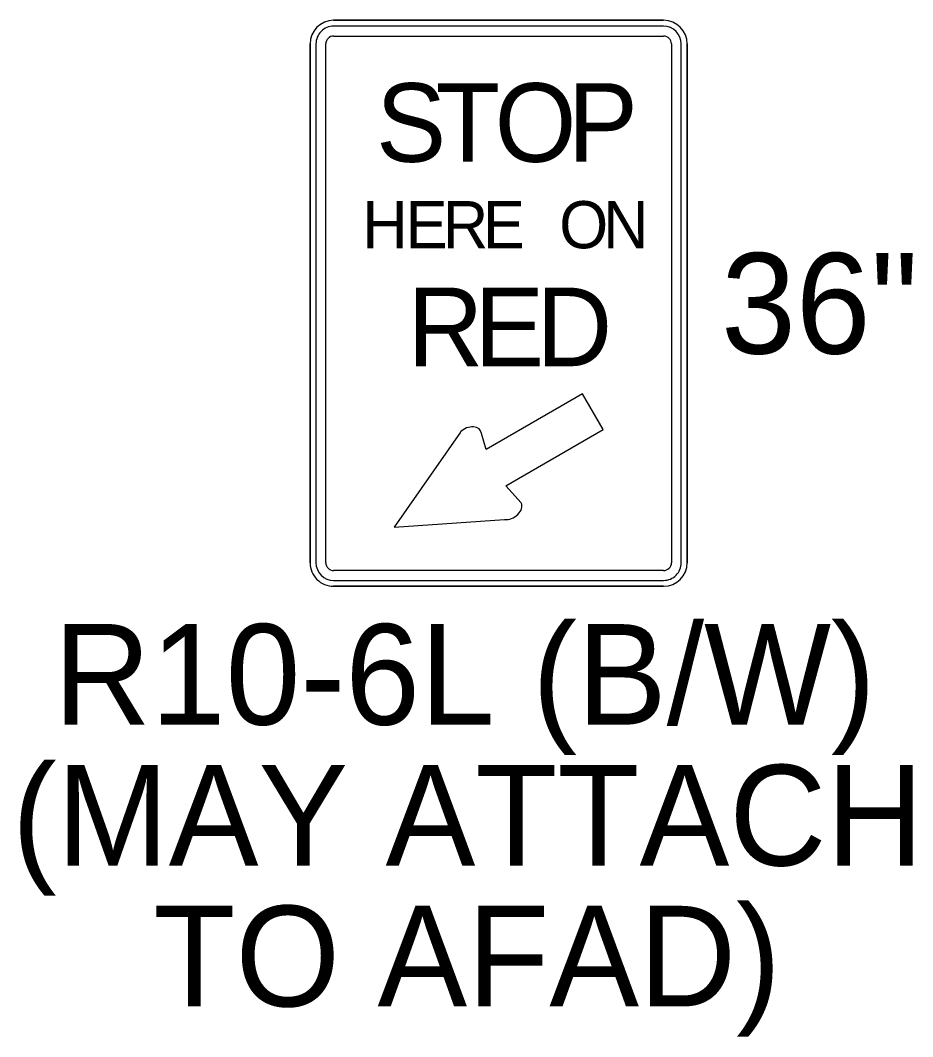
# Model space of a CAD drawing. Extents: x 99999.1 to 100095.7, y 99995 to 100010.7.
# Drawn here: x 100043.892 to 100044.602, y 100003.772 to 100004.58 of the extents above; entities that cross this region are included whole.
import ezdxf

# ---------------------------------------------------------------- set-up
doc = ezdxf.new("R2010")
doc.units = 0
doc.layers.add('TR_SN_ConstructionSigns', color=7, linetype='Continuous')

msp = doc.modelspace()

# ---------------------------------------------------------------- linework, layer by layer
at = {"layer": 'TR_SN_ConstructionSigns'}
for p, q in [((100044.40413, 100004.57961), (100044.14163, 100004.57961)), ((100044.14163, 100004.57961), (100044.40413, 100004.57961)), ((100044.40413, 100004.57961), (100044.14163, 100004.57961)), ((100044.40413, 100004.57493), (100044.14163, 100004.57493)), ((100044.14163, 100004.56711), (100044.40413, 100004.56711)), ((100044.12288, 100004.56086), (100044.12288, 100004.14836)), ((100044.12288, 100004.14836), (100044.12288, 100004.56086)), ((100044.12288, 100004.56086), (100044.12288, 100004.14836)), ((100044.12756, 100004.56086), (100044.12756, 100004.14836)), ((100044.13538, 100004.14836), (100044.13538, 100004.56086)), ((100044.41038, 100004.56086), (100044.41038, 100004.14836)), ((100044.41819, 100004.14836), (100044.41819, 100004.56086)), ((100044.42288, 100004.14836), (100044.42288, 100004.56086)), ((100044.42288, 100004.56086), (100044.42288, 100004.14836)), ((100044.42288, 100004.14836), (100044.42288, 100004.56086)), ((100044.33959, 100004.28269), (100044.26297, 100004.23846)), ((100044.356, 100004.25428), (100044.33959, 100004.28269)), ((100044.24244, 100004.2523), (100044.18976, 100004.1766)), ((100044.26297, 100004.23846), (100044.2592, 100004.25114)), ((100044.27857, 100004.20957), (100044.356, 100004.25428)), ((100044.29088, 100004.19589), (100044.27857, 100004.20957)), ((100044.18976, 100004.1766), (100044.27762, 100004.1827)), ((100044.40413, 100004.14211), (100044.14163, 100004.14211)), ((100044.14163, 100004.1343), (100044.40413, 100004.1343)), ((100044.14163, 100004.12961), (100044.40413, 100004.12961)), ((100044.40413, 100004.12961), (100044.14163, 100004.12961)), ((100044.14163, 100004.12961), (100044.40413, 100004.12961))]:
    msp.add_line(p, q, dxfattribs=at)
for centre, radius, start, end in [((100044.14163, 100004.56086), 0.01875, 90, 180), ((100044.14163, 100004.56086), 0.01875, 90, 180), ((100044.14163, 100004.56086), 0.01875, 90, 180), ((100044.14163, 100004.56086), 0.01406, 90, 180.00001), ((100044.40413, 100004.56086), 0.01875, 0, 90), ((100044.40413, 100004.56086), 0.01875, 0, 90), ((100044.40413, 100004.56086), 0.01875, 0, 90), ((100044.40413, 100004.56086), 0.01406, 0, 90), ((100044.14163, 100004.56086), 0.00625, 90, 180.00001), ((100044.40413, 100004.56086), 0.00625, 0, 90), ((100044.14163, 100004.14836), 0.01875, 180, 270.00001), ((100044.14163, 100004.14836), 0.01875, 180, 270.00001), ((100044.14163, 100004.14836), 0.01875, 180, 270.00001), ((100044.14163, 100004.14836), 0.01406, 180.00001, 270), ((100044.14163, 100004.14836), 0.00625, 180.00001, 270), ((100044.40413, 100004.14836), 0.01875, 270.00001, 0.00001), ((100044.40413, 100004.14836), 0.01875, 270.00001, 0.00001), ((100044.40413, 100004.14836), 0.01875, 270.00001, 0.00001), ((100044.40413, 100004.14836), 0.01406, 270, 0.00001), ((100044.40413, 100004.14836), 0.00625, 270, 0.00001)]:
    msp.add_arc(centre, radius, start, end, dxfattribs=at)
for centre, major_axis, start_param, end_param in [((100044.24915, 100004.24797), (0.00934, 0.00539), 5.977036, 8.198856), ((100044.28158, 100004.19094), (-0.00913, -0.00527), 0.771965, 3.092601)]:
    msp.add_ellipse(centre, major_axis=major_axis, ratio=0.700347, start_param=start_param, end_param=end_param, dxfattribs=at)

# ---------------------------------------------------------------- texts
for s, height, p in [('S', 0.0625, (100044.17538, 100004.46711)), ('T', 0.0625, (100044.22288, 100004.46711)), ('O', 0.0625, (100044.26975, 100004.46711)), ('P', 0.0625, (100044.32788, 100004.46711)), ('H', 0.0375, (100044.16431, 100004.39836)), ('E', 0.0375, (100044.19881, 100004.39836)), ('R', 0.0375, (100044.22844, 100004.39836)), ('E', 0.0375, (100044.26031, 100004.39836)), ('O', 0.0375, (100044.32106, 100004.39836)), ('N', 0.0375, (100044.35594, 100004.39836)), ('R', 0.0625, (100044.20038, 100004.30461)), ('E', 0.0625, (100044.2535, 100004.30461)), ('D', 0.0625, (100044.30288, 100004.30461))]:
    msp.add_text(s, height=height, dxfattribs=at).set_placement(p)
for s, p in [('36"', (100044.44981, 100004.31461)), ('R10-6L (B/W)', (100043.919, 100004.01961)), ('(MAY ATTACH', (100043.88578, 100003.90761)), ('TO AFAD)', (100043.99821, 100003.79561))]:
    msp.add_text(s, height=0.08, rotation=360, dxfattribs=at).set_placement(p)

doc.saveas('drawing.dxf')
